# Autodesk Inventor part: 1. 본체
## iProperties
Created: 2014-12
Part Number: 1. 본체
Document SubType Name: Modeling
Designer: elite
Density: 2.71 g/cm^3
Material: 알루미늄-6061
Mass: 613.439 g
Surface Area: 665.18 cm^2
Volume: 226.361 cm^3
Author: elite
